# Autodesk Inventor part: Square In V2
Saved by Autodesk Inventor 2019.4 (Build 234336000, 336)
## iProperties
Created: 2020-12
Part Number: Square In V2
Material: Generic
Document SubType Name: Modeling
Designer: Administrator
Density: 1 g/cm^3
Appearance: Default
Title: Square In V2
Author: Administrator
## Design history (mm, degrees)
feature "Body1"
feature "Body2"
body "Solid1"
body "Solid2"
